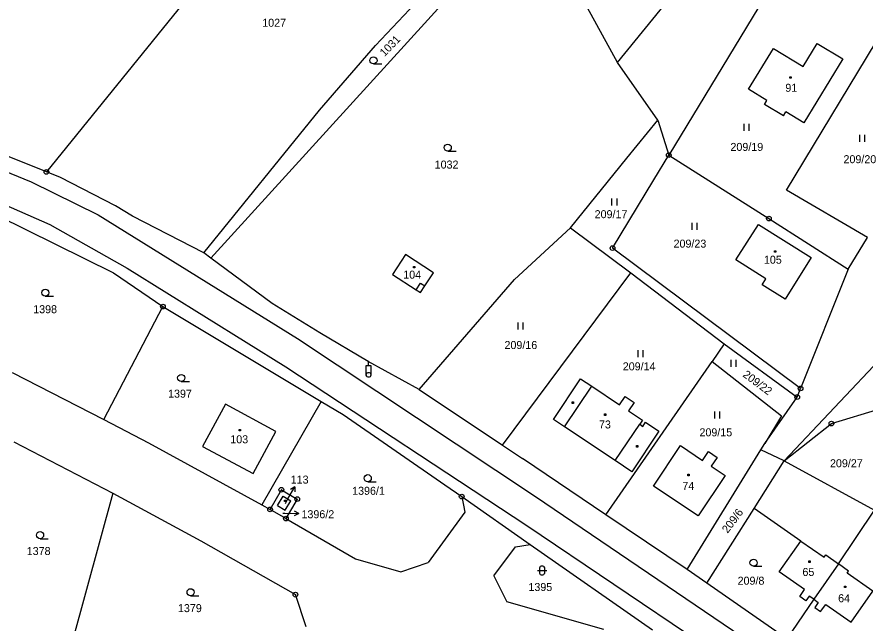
# Model space of a CAD drawing. Extents: x -796130 to -793145, y -1109506 to -1106267.
# Drawn here: x -794845 to -794664.8, y -1107604.2 to -1107475.5 of the extents above; entities that cross this region are included whole.
import ezdxf

# ---------------------------------------------------------------- set-up
doc = ezdxf.new("R2010")
doc.units = 0
for name, color, linetype in [('Komunikace', 7, 'Continuous'), ('Vrstva 1', 7, 'Continuous'), ('Vrstva 14', 7, 'Continuous'), ('Vrstva 15', 7, 'Continuous'), ('Vrstva 16', 7, 'Continuous'), ('Vrstva 2', 7, 'Continuous'), ('Vrstva 23', 7, 'Continuous'), ('Vrstva 25', 7, 'Continuous'), ('Vrstva 26', 7, 'Continuous'), ('Vrstva 28', 7, 'Continuous')]:
    doc.layers.add(name, color=color, linetype=linetype)

msp = doc.modelspace()

# ---------------------------------------------------------------- linework, layer by layer
at = {"layer": 'Komunikace'}
for p, q in [((-794787.93, -1107578.82), (-794787.4, -1107577.89)), ((-794788.52, -1107580.9), (-794788.06, -1107580.91))]:
    msp.add_line(p, q, dxfattribs=at)
at = {"layer": 'Vrstva 1'}
for p, q in [((-794771.57, -1107425.45), (-794838.71, -1107508.42)), ((-794717.39, -1107485.15), (-794682.07, -1107441.58)), ((-794672.72, -1107449.16), (-794706.54, -1107504.86)), ((-794803.77, -1107526.73), (-794737.76, -1107454.19)), ((-794717.39, -1107485.15), (-794728.31, -1107465.29)), ((-794681.54, -1107512.28), (-794653.59, -1107465.98)), ((-794768.82, -1107481.58), (-794758.5, -1107470.63)), ((-794780.72, -1107495.31), (-794768.82, -1107481.58)), ((-794678, -1107486.03), (-794674.99, -1107481.11)), ((-794674.99, -1107481.11), (-794669.53, -1107484.43)), ((-794689.57, -1107490.85), (-794684.31, -1107482.18)), ((-794684.31, -1107482.18), (-794678, -1107486.03)), ((-794708.88, -1107497.45), (-794717.39, -1107485.15)), ((-794669.53, -1107484.43), (-794677.82, -1107498.02)), ((-794685.68, -1107493.22), (-794689.57, -1107490.85)), ((-794686.21, -1107494.07), (-794685.68, -1107493.22)), ((-794682.19, -1107496.54), (-794686.21, -1107494.07)), ((-794805.25, -1107525.63), (-794780.72, -1107495.31)), ((-794682.19, -1107496.54), (-794681.68, -1107495.68)), ((-794677.82, -1107498.02), (-794681.68, -1107495.68)), ((-794838.71, -1107508.42), (-794866.75, -1107497.21)), ((-794715.41, -1107505.51), (-794708.88, -1107497.45)), ((-794708.88, -1107497.45), (-794706.54, -1107504.86)), ((-794727.42, -1107520.33), (-794715.41, -1107505.51)), ((-794709.69, -1107510.08), (-794706.54, -1107504.86)), ((-794706.54, -1107504.86), (-794685.25, -1107518.33)), ((-794835.69, -1107509.62), (-794838.71, -1107508.42)), ((-794824.06, -1107515.64), (-794835.69, -1107509.62)), ((-794718.47, -1107524.61), (-794709.69, -1107510.08)), ((-794664.34, -1107522.36), (-794681.54, -1107512.28)), ((-794852.58, -1107515.99), (-794824.49, -1107529.82)), ((-794820.4, -1107517.81), (-794824.06, -1107515.64)), ((-794805.25, -1107525.63), (-794820.4, -1107517.81)), ((-794692.26, -1107527.11), (-794687.5, -1107519.59)), ((-794687.5, -1107519.59), (-794676.28, -1107526.62)), ((-794685.25, -1107518.33), (-794668.4, -1107529.11)), ((-794739.29, -1107531.26), (-794727.42, -1107520.33)), ((-794727.42, -1107520.33), (-794714.57, -1107529.89)), ((-794668.4, -1107529.11), (-794664.34, -1107522.36)), ((-794678.53, -1107554.4), (-794718.47, -1107524.61)), ((-794803.77, -1107526.73), (-794805.25, -1107525.63)), ((-794790.73, -1107536.39), (-794803.77, -1107526.73)), ((-794762.46, -1107525.99), (-794765.19, -1107530.2)), ((-794756.52, -1107529.85), (-794762.46, -1107525.99)), ((-794685.88, -1107531.11), (-794692.26, -1107527.11)), ((-794676.28, -1107526.62), (-794681.8, -1107535.43)), ((-794824.49, -1107529.82), (-794813.96, -1107537.03)), ((-794765.19, -1107530.2), (-794760.15, -1107533.47)), ((-794758.32, -1107532.63), (-794756.52, -1107529.85)), ((-794741.83, -1107566.44), (-794714.57, -1107529.89)), ((-794714.57, -1107529.89), (-794694.74, -1107544.93)), ((-794668.4, -1107529.11), (-794678.53, -1107554.4)), ((-794759.51, -1107554.67), (-794739.29, -1107531.26)), ((-794686.67, -1107532.38), (-794685.88, -1107531.11)), ((-794681.8, -1107535.43), (-794686.67, -1107532.38)), ((-794760.15, -1107533.47), (-794759.23, -1107534.04)), ((-794759.23, -1107534.04), (-794758.32, -1107532.63)), ((-794826.51, -1107561), (-794813.96, -1107537.03)), ((-794813.96, -1107537.03), (-794780.32, -1107557.16)), ((-794780.66, -1107542.58), (-794790.73, -1107536.39)), ((-794770.34, -1107548.71), (-794780.66, -1107542.58)), ((-794694.74, -1107544.93), (-794697.33, -1107548.68)), ((-794694.74, -1107544.93), (-794679.25, -1107556.25)), ((-794681.99, -1107569.82), (-794658.54, -1107544.85)), ((-794759.51, -1107554.67), (-794770.34, -1107548.71)), ((-794719.92, -1107581.26), (-794697.33, -1107548.68)), ((-794697.33, -1107548.68), (-794682.56, -1107560.22)), ((-794846, -1107551.02), (-794826.51, -1107561)), ((-794731.03, -1107560.98), (-794725.25, -1107552.37)), ((-794725.25, -1107552.37), (-794722.89, -1107553.95)), ((-794722.89, -1107553.95), (-794716.97, -1107557.92)), ((-794759.51, -1107554.67), (-794741.83, -1107566.44)), ((-794679.25, -1107556.25), (-794678.53, -1107554.4)), ((-794800.7, -1107557.73), (-794805.53, -1107566.73)), ((-794790.01, -1107563.54), (-794800.7, -1107557.73)), ((-794780.32, -1107557.16), (-794792.94, -1107579.11)), ((-794780.32, -1107557.16), (-794775.69, -1107559.93)), ((-794716.97, -1107557.92), (-794715.77, -1107556.13)), ((-794715.77, -1107556.13), (-794713.91, -1107557.38)), ((-794713.91, -1107557.38), (-794715.11, -1107559.16)), ((-794686.14, -1107566.13), (-794679.25, -1107556.25)), ((-794715.11, -1107559.16), (-794712.12, -1107561.16)), ((-794671.99, -1107561.86), (-794661.68, -1107558.71)), ((-794826.51, -1107561), (-794817.05, -1107565.95)), ((-794775.69, -1107559.93), (-794754.1, -1107574.89)), ((-794728.66, -1107562.56), (-794731.03, -1107560.98)), ((-794712.12, -1107561.16), (-794712.7, -1107562.03)), ((-794682.56, -1107560.22), (-794686.14, -1107566.13)), ((-794717.94, -1107569.73), (-794728.66, -1107562.56)), ((-794712.7, -1107562.03), (-794712.04, -1107562.47)), ((-794712.04, -1107562.47), (-794711.46, -1107561.6)), ((-794711.46, -1107561.6), (-794708.62, -1107563.52)), ((-794681.99, -1107569.82), (-794671.99, -1107561.86)), ((-794794.77, -1107572.51), (-794790.01, -1107563.54)), ((-794708.62, -1107563.52), (-794714.37, -1107572.12)), ((-794845.65, -1107565.77), (-794824.63, -1107576.66)), ((-794817.05, -1107565.95), (-794792.94, -1107579.11)), ((-794805.53, -1107566.73), (-794794.77, -1107572.51)), ((-794741.83, -1107566.44), (-794737.59, -1107569.27)), ((-794709.75, -1107575.2), (-794704.01, -1107566.55)), ((-794704.01, -1107566.55), (-794699.35, -1107569.7)), ((-794686.97, -1107567.47), (-794686.14, -1107566.13)), ((-794702.65, -1107592.84), (-794686.97, -1107567.47)), ((-794699.35, -1107569.7), (-794698.08, -1107567.81)), ((-794698.08, -1107567.81), (-794696.23, -1107569.05)), ((-794681.99, -1107569.82), (-794686.97, -1107567.47)), ((-794719.92, -1107581.26), (-794737.59, -1107569.27)), ((-794714.37, -1107572.12), (-794717.94, -1107569.73)), ((-794696.23, -1107569.05), (-794697.51, -1107570.94)), ((-794688.38, -1107579.91), (-794681.99, -1107569.82)), ((-794681.99, -1107569.82), (-794662.84, -1107580.24)), ((-794697.51, -1107570.94), (-794694.58, -1107572.91)), ((-794694.58, -1107572.91), (-794700.3, -1107581.47)), ((-794754.1, -1107574.89), (-794750.51, -1107577.39)), ((-794700.3, -1107581.47), (-794709.75, -1107575.2)), ((-794824.63, -1107576.66), (-794833.09, -1107607.75)), ((-794824.63, -1107576.66), (-794805.88, -1107586.79)), ((-794791.21, -1107580.11), (-794788.81, -1107575.93)), ((-794789.62, -1107579.28), (-794788.42, -1107577.29)), ((-794788.81, -1107575.93), (-794785.43, -1107577.9)), ((-794788.42, -1107577.29), (-794786.78, -1107578.28)), ((-794750.51, -1107577.39), (-794735.95, -1107587.55)), ((-794750.51, -1107577.39), (-794749.87, -1107580.72)), ((-794792.94, -1107579.11), (-794791.21, -1107580.11)), ((-794789.62, -1107579.28), (-794788, -1107580.25)), ((-794788, -1107580.25), (-794786.78, -1107578.28)), ((-794785.43, -1107577.9), (-794787.83, -1107582.06)), ((-794787.83, -1107582.06), (-794791.21, -1107580.11)), ((-794749.87, -1107580.72), (-794757.65, -1107591.4)), ((-794698.42, -1107595.76), (-794688.38, -1107579.91)), ((-794678.47, -1107586.84), (-794688.38, -1107579.91)), ((-794670.51, -1107591.63), (-794662.84, -1107580.24)), ((-794787.83, -1107582.06), (-794773.09, -1107590.58)), ((-794702.65, -1107592.84), (-794719.92, -1107581.26)), ((-794805.88, -1107586.79), (-794785.81, -1107598.21)), ((-794743.66, -1107594.24), (-794739.11, -1107588.03)), ((-794739.11, -1107588.03), (-794735.95, -1107587.55)), ((-794735.95, -1107587.55), (-794710.01, -1107605.65)), ((-794683.05, -1107593.39), (-794678.47, -1107586.84)), ((-794773.09, -1107590.58), (-794763.46, -1107593.33)), ((-794763.46, -1107593.33), (-794757.65, -1107591.4)), ((-794670.51, -1107591.63), (-794675.74, -1107599.18)), ((-794698.42, -1107595.76), (-794702.65, -1107592.84)), ((-794677.68, -1107597.15), (-794683.05, -1107593.39)), ((-794743.66, -1107594.24), (-794740.92, -1107599.75)), ((-794681.46, -1107607.59), (-794698.42, -1107595.76)), ((-794678.68, -1107598.59), (-794677.68, -1107597.15)), ((-794783.56, -1107605.02), (-794785.81, -1107598.21)), ((-794675.74, -1107599.18), (-794681.46, -1107607.59)), ((-794677.39, -1107599.49), (-794678.68, -1107598.59)), ((-794676.71, -1107598.51), (-794677.39, -1107599.49)), ((-794675.74, -1107599.18), (-794676.71, -1107598.51)), ((-794675.74, -1107599.18), (-794674.78, -1107599.85)), ((-794667.79, -1107604.08), (-794663.22, -1107597.48)), ((-794720.31, -1107605.63), (-794740.92, -1107599.75)), ((-794674.78, -1107599.85), (-794675.54, -1107600.94)), ((-794675.54, -1107600.94), (-794674.27, -1107601.82)), ((-794674.27, -1107601.82), (-794673.2, -1107600.29)), ((-794673.2, -1107600.29), (-794667.79, -1107604.08))]:
    msp.add_line(p, q, dxfattribs=at)
at = {"layer": 'Vrstva 16'}
for p, q in [((-794787.4, -1107577.89), (-794785.924, -1107575.278)), ((-794785.924, -1107575.278), (-794786.851, -1107575.902)), ((-794785.924, -1107575.278), (-794785.98, -1107576.394)), ((-794788.06, -1107580.91), (-794785.061, -1107580.996)), ((-794785.061, -1107580.996), (-794786.075, -1107581.467)), ((-794785.061, -1107580.996), (-794786.046, -1107580.468))]:
    msp.add_line(p, q, dxfattribs=at)
at = {"layer": 'Vrstva 2'}
for p, q in [((-794884.26, -1107493.46), (-794841.93, -1107510.52)), ((-794859.11, -1107510.35), (-794837.96, -1107519.62)), ((-794841.93, -1107510.52), (-794827.68, -1107517.54)), ((-794827.68, -1107517.54), (-794785.41, -1107543.82)), ((-794837.96, -1107519.62), (-794821.52, -1107528.87)), ((-794821.52, -1107528.87), (-794787.85, -1107549.84)), ((-794760.15, -1107533.47), (-794759.25, -1107532.04)), ((-794759.25, -1107532.04), (-794758.32, -1107532.63)), ((-794785.41, -1107543.82), (-794734.8, -1107577.36)), ((-794787.85, -1107549.84), (-794736.64, -1107583.51)), ((-794728.66, -1107562.56), (-794722.89, -1107553.95)), ((-794717.94, -1107569.73), (-794712.7, -1107562.03)), ((-794734.8, -1107577.36), (-794667.89, -1107622.77)), ((-794736.64, -1107583.51), (-794671.21, -1107627.61)), ((-794678.47, -1107586.84), (-794673.54, -1107590.28)), ((-794673.54, -1107590.28), (-794673.18, -1107589.77)), ((-794673.18, -1107589.77), (-794670.51, -1107591.63)), ((-794668.33, -1107593.19), (-794670.51, -1107591.63)), ((-794668.67, -1107593.68), (-794668.33, -1107593.19)), ((-794663.22, -1107597.48), (-794668.67, -1107593.68))]:
    msp.add_line(p, q, dxfattribs=at)
at = {"layer": 'Vrstva 23'}
for p, q in [((-794769.24, -1107485.48), (-794767.49, -1107485.48)), ((-794690.5, -1107499.71), (-794690.5, -1107498.21)), ((-794689.5, -1107498.21), (-794689.5, -1107499.71)), ((-794665.94, -1107502.04), (-794665.94, -1107500.54)), ((-794664.94, -1107500.54), (-794664.94, -1107502.04)), ((-794753.46, -1107504.01), (-794751.71, -1107504.01)), ((-794718.59, -1107515.57), (-794718.59, -1107514.07)), ((-794717.59, -1107514.07), (-794717.59, -1107515.57)), ((-794701.59, -1107520.74), (-794701.59, -1107519.24)), ((-794700.59, -1107519.24), (-794700.59, -1107520.74)), ((-794838.94, -1107534.82), (-794837.19, -1107534.82)), ((-794738.49, -1107541.92), (-794738.49, -1107540.42)), ((-794737.49, -1107540.42), (-794737.49, -1107541.92)), ((-794713.04, -1107547.78), (-794713.04, -1107546.28)), ((-794712.04, -1107546.28), (-794712.04, -1107547.78)), ((-794693.31, -1107549.85), (-794693.31, -1107548.35)), ((-794692.31, -1107548.35), (-794692.31, -1107549.85)), ((-794810.08, -1107552.93), (-794808.33, -1107552.93)), ((-794696.74, -1107560.81), (-794696.74, -1107559.31)), ((-794695.74, -1107559.31), (-794695.74, -1107560.81)), ((-794770.45, -1107574.22), (-794768.7, -1107574.22)), ((-794840.05, -1107586.32), (-794838.3, -1107586.32)), ((-794734.44, -1107593.09), (-794732.44, -1107593.09)), ((-794733.94, -1107592.49), (-794733.84, -1107592.29)), ((-794733.94, -1107593.69), (-794733.94, -1107592.49)), ((-794733.84, -1107593.89), (-794733.94, -1107593.69)), ((-794733.84, -1107592.29), (-794733.74, -1107592.19)), ((-794733.74, -1107592.19), (-794733.54, -1107592.09)), ((-794733.54, -1107592.09), (-794733.34, -1107592.09)), ((-794733.34, -1107592.09), (-794733.14, -1107592.19)), ((-794733.14, -1107592.19), (-794733.04, -1107592.29)), ((-794733.04, -1107592.29), (-794732.94, -1107592.49)), ((-794732.94, -1107593.69), (-794733.04, -1107593.89)), ((-794732.94, -1107592.49), (-794732.94, -1107593.69)), ((-794688.53, -1107592.18), (-794686.78, -1107592.18)), ((-794733.74, -1107593.99), (-794733.84, -1107593.89)), ((-794733.54, -1107594.09), (-794733.74, -1107593.99)), ((-794733.34, -1107594.09), (-794733.54, -1107594.09)), ((-794733.14, -1107593.99), (-794733.34, -1107594.09)), ((-794733.04, -1107593.89), (-794733.14, -1107593.99)), ((-794808.09, -1107598.45), (-794806.34, -1107598.45))]:
    msp.add_line(p, q, dxfattribs=at)
for centre in [(-794769.24, -1107484.73), (-794753.46, -1107503.26), (-794838.94, -1107534.07), (-794810.08, -1107552.18), (-794770.45, -1107573.47), (-794840.05, -1107585.57), (-794688.53, -1107591.43), (-794808.09, -1107597.7)]:
    msp.add_circle(centre, 0.75, dxfattribs=at)
at = {"layer": 'Vrstva 25'}
for p, q in [((-794680.84, -1107488.22), (-794680.54, -1107488.22)), ((-794680.84, -1107488.52), (-794680.84, -1107488.22)), ((-794680.54, -1107488.52), (-794680.84, -1107488.52)), ((-794680.54, -1107488.22), (-794680.54, -1107488.52)), ((-794684.06, -1107525.18), (-794683.76, -1107525.18)), ((-794684.06, -1107525.48), (-794684.06, -1107525.18)), ((-794683.76, -1107525.18), (-794683.76, -1107525.48)), ((-794683.76, -1107525.48), (-794684.06, -1107525.48)), ((-794760.76, -1107528.51), (-794760.46, -1107528.51)), ((-794760.76, -1107528.81), (-794760.76, -1107528.51)), ((-794760.46, -1107528.81), (-794760.76, -1107528.81)), ((-794760.46, -1107528.51), (-794760.46, -1107528.81)), ((-794727.05, -1107557.29), (-794726.75, -1107557.29)), ((-794727.05, -1107557.59), (-794727.05, -1107557.29)), ((-794726.75, -1107557.59), (-794727.05, -1107557.59)), ((-794726.75, -1107557.29), (-794726.75, -1107557.59)), ((-794720.19, -1107559.83), (-794719.89, -1107559.83)), ((-794720.19, -1107560.13), (-794720.19, -1107559.83)), ((-794719.89, -1107560.13), (-794720.19, -1107560.13)), ((-794719.89, -1107559.83), (-794719.89, -1107560.13)), ((-794797.77, -1107563.1), (-794797.47, -1107563.1)), ((-794797.77, -1107563.4), (-794797.77, -1107563.1)), ((-794797.47, -1107563.1), (-794797.47, -1107563.4)), ((-794797.47, -1107563.4), (-794797.77, -1107563.4)), ((-794713.4, -1107566.55), (-794713.1, -1107566.55)), ((-794713.4, -1107566.85), (-794713.4, -1107566.55)), ((-794713.1, -1107566.55), (-794713.1, -1107566.85)), ((-794713.1, -1107566.85), (-794713.4, -1107566.85)), ((-794702.51, -1107572.65), (-794702.21, -1107572.65)), ((-794702.51, -1107572.95), (-794702.51, -1107572.65)), ((-794702.21, -1107572.95), (-794702.51, -1107572.95)), ((-794702.21, -1107572.65), (-794702.21, -1107572.95)), ((-794788.15, -1107578.16), (-794787.85, -1107578.16)), ((-794788.15, -1107578.46), (-794788.15, -1107578.16)), ((-794787.85, -1107578.46), (-794788.15, -1107578.46)), ((-794787.85, -1107578.16), (-794787.85, -1107578.46)), ((-794676.79, -1107591.05), (-794676.49, -1107591.05)), ((-794676.79, -1107591.35), (-794676.79, -1107591.05)), ((-794676.49, -1107591.35), (-794676.79, -1107591.35)), ((-794676.49, -1107591.05), (-794676.49, -1107591.35)), ((-794669.22, -1107596.42), (-794668.92, -1107596.42)), ((-794669.22, -1107596.72), (-794669.22, -1107596.42)), ((-794668.92, -1107596.72), (-794669.22, -1107596.72)), ((-794668.92, -1107596.42), (-794668.92, -1107596.72))]:
    msp.add_line(p, q, dxfattribs=at)
at = {"layer": 'Vrstva 26'}
for p, q in [((-794770.28, -1107549.52), (-794770.28, -1107548.52)), ((-794770.78, -1107551.52), (-794770.78, -1107549.52)), ((-794770.78, -1107549.52), (-794769.78, -1107549.52)), ((-794769.78, -1107549.52), (-794769.78, -1107551.52)), ((-794770.78, -1107551.42), (-794770.68, -1107551.22)), ((-794770.78, -1107551.62), (-794770.78, -1107551.42)), ((-794770.68, -1107551.82), (-794770.78, -1107551.62)), ((-794770.68, -1107551.22), (-794770.58, -1107551.12)), ((-794770.58, -1107551.92), (-794770.68, -1107551.82)), ((-794770.58, -1107551.12), (-794770.38, -1107551.02)), ((-794770.38, -1107552.02), (-794770.58, -1107551.92)), ((-794770.38, -1107551.02), (-794770.18, -1107551.02)), ((-794770.18, -1107552.02), (-794770.38, -1107552.02)), ((-794770.28, -1107551.52), (-794770.28, -1107551.52)), ((-794770.18, -1107551.02), (-794769.98, -1107551.12)), ((-794769.98, -1107551.92), (-794770.18, -1107552.02)), ((-794769.98, -1107551.12), (-794769.88, -1107551.22)), ((-794769.88, -1107551.82), (-794769.98, -1107551.92)), ((-794769.88, -1107551.22), (-794769.78, -1107551.42)), ((-794769.78, -1107551.62), (-794769.88, -1107551.82)), ((-794769.78, -1107551.42), (-794769.78, -1107551.62))]:
    msp.add_line(p, q, dxfattribs=at)
at = {"layer": 'Vrstva 28'}
for centre, radius in [((-794706.54, -1107504.86), 0.5), ((-794706.54, -1107504.86), 0.5), ((-794706.54, -1107504.86), 0.01), ((-794706.54, -1107504.86), 0.01), ((-794838.71, -1107508.42), 0.5), ((-794838.71, -1107508.42), 0.01), ((-794685.25, -1107518.33), 0.5), ((-794685.25, -1107518.33), 0.01), ((-794718.47, -1107524.61), 0.5), ((-794718.47, -1107524.61), 0.01), ((-794813.96, -1107537.03), 0.5), ((-794813.96, -1107537.03), 0.01), ((-794678.53, -1107554.4), 0.5), ((-794679.25, -1107556.25), 0.5), ((-794678.53, -1107554.4), 0.01), ((-794679.25, -1107556.25), 0.01), ((-794671.99, -1107561.86), 0.5), ((-794671.99, -1107561.86), 0.01), ((-794788.81, -1107575.93), 0.5), ((-794788.81, -1107575.93), 0.01), ((-794785.43, -1107577.9), 0.5), ((-794750.51, -1107577.39), 0.5), ((-794750.51, -1107577.39), 0.01), ((-794785.43, -1107577.9), 0.01), ((-794791.21, -1107580.11), 0.5), ((-794791.21, -1107580.11), 0.01), ((-794787.83, -1107582.06), 0.5), ((-794787.83, -1107582.06), 0.01), ((-794785.81, -1107598.21), 0.5), ((-794785.81, -1107598.21), 0.01)]:
    msp.add_circle(centre, radius, dxfattribs=at)

# ---------------------------------------------------------------- texts
at = {"layer": 'Vrstva 14'}
for s, height, p in [('1027', 1.7, (-794792.865, -1107477.59)), ('209/19', 1.7, (-794693.43, -1107503.96)), ('209/20', 1.7, (-794669.42, -1107506.57)), ('1032', 1.7, (-794756.249, -1107507.71)), ('209/17', 1.7, (-794722.27, -1107518.25)), ('209/23', 1.7, (-794705.51, -1107524.5)), ('1398', 1.7, (-794841.51, -1107538.43)), ('209/16', 1.7, (-794741.42, -1107546.04)), ('209/14', 1.7, (-794716.3, -1107550.57)), ('1397', 1.7, (-794812.866, -1107556.37)), ('209/15', 1.7, (-794700.01, -1107564.58)), ('209/27', 1.7, (-794672.29, -1107571.15)), ('1396/1', 1.7, (-794773.776, -1107577)), ('1396/2', 0.1, (-794788.756, -1107580.9)), ('1378', 1.7, (-794842.886, -1107589.8)), ('209/8', 1.7, (-794691.91, -1107596.1)), ('1395', 1.7, (-794736.336, -1107597.44)), ('1379', 1.7, (-794810.766, -1107601.92))]:
    msp.add_text(s, height=height, dxfattribs=at).set_placement(p)
for s, rotation, p in [('1031', 45.9, (-794766.894, -1107484.041)), ('209/22', 323.13006, (-794690.95, -1107551.77)), ('209/6', 52.95375, (-794694.03, -1107585.28))]:
    msp.add_text(s, height=1.7, rotation=rotation, dxfattribs=at).set_placement(p)
at = {"layer": 'Vrstva 15'}
for s, height, p in [('91', 1.7, (-794681.77, -1107491.4)), ('105', 1.7, (-794686.325, -1107527.92)), ('104', 1.7, (-794762.915, -1107531.09)), ('73', 1.7, (-794721.35, -1107562.91)), ('103', 1.7, (-794799.649, -1107566.06)), ('74', 1.7, (-794703.65, -1107575.97)), ('113', 0.1, (-794788.032, -1107578.82)), ('65', 1.7, (-794678.14, -1107594.24)), ('64', 1.7, (-794670.56, -1107599.82))]:
    msp.add_text(s, height=height, dxfattribs=at).set_placement(p)
at = {"layer": 'Vrstva 16'}
for s, p in [('113', (-794786.823, -1107574.62)), ('1396/2', (-794784.533, -1107581.98))]:
    msp.add_text(s, height=1.7, dxfattribs=at).set_placement(p)

doc.saveas('drawing.dxf')
